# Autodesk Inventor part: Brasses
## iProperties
Shininess: 77.0
Length Units: 11269
Angle Units: 11279
Time Units: 11290
Mass Units: 11283
Length Display Precision: 3
Angle Display Precision: 2
Created: 2002-02
Part Number: Brasses
Document SubType Name: Modeling
Designer: ***
Stock Number: 01
Density: 0.0
Volumn: 0.0
Area: 0.0
PropertySet Name: Model Information
Control State: 0
Master: False
Checked Out: False
Author: ***
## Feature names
1. Revolution1
2. Hole1
3. Extrusion1
4. Hole2
